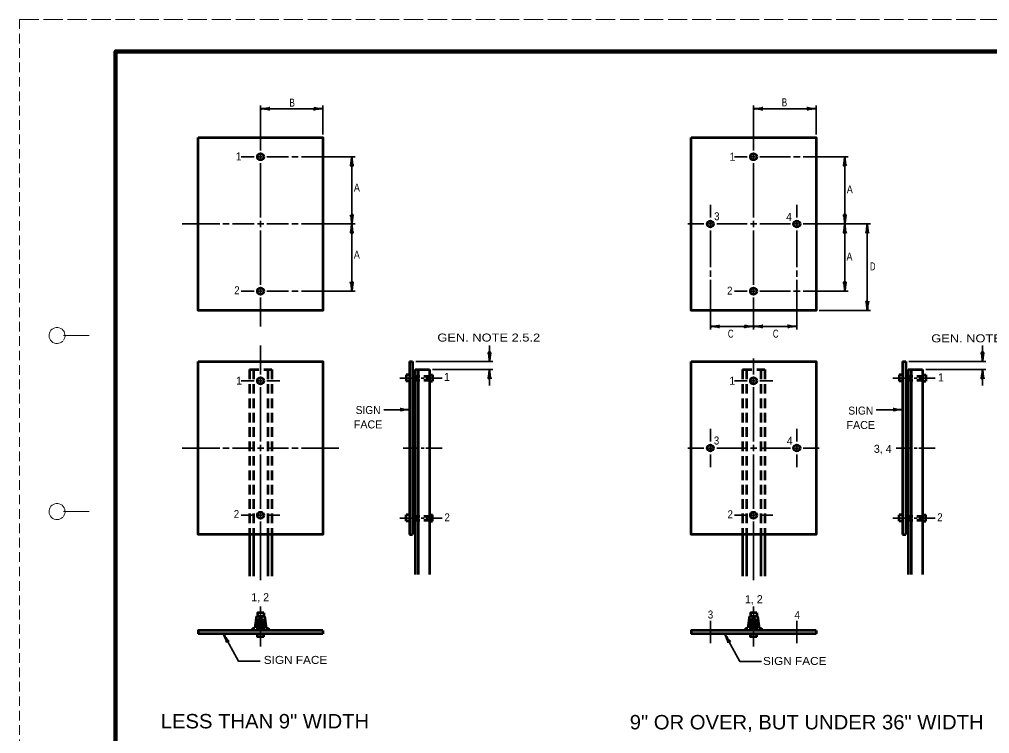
# Model space of a CAD drawing. Extents: x -45 to 635, y -378 to 62.
# Drawn here: x -45.3 to 257.7, y -160.7 to 62.5 of the extents above; entities that cross this region are included whole.
import ezdxf
from ezdxf.enums import TextEntityAlignment as Align

# ---------------------------------------------------------------- set-up
doc = ezdxf.new("R2010")
doc.units = 0
for name, pattern in [('LONG_DASHED', [7.5, 6, -1.5]), ('MEDIUM_DASHED', [4.5, 3, -1.5]), ('SHORT_DASHED', [2.7, 1.5, -1.2])]:
    doc.linetypes.add(name, pattern=pattern)
doc.layers.add('1', color=7, linetype='Continuous', lineweight=53)
doc.layers.add('61', color=7, linetype='Continuous', lineweight=35)

msp = doc.modelspace()

# ---------------------------------------------------------------- linework, layer by layer
at = {"layer": '1', "linetype": 'MEDIUM_DASHED', "lineweight": 13}
msp.add_line((-45.266, 62.46), (-45.326, -377.58), dxfattribs=at)
at = {"layer": '1', "lineweight": 35}
for p, q in [((29.979, 35.543), (29.979, 21.543)), ((29.979, 34.543), (49.479, 34.543)), ((49.479, 26.543), (49.479, 35.543)), ((183.951, 35.543), (183.951, 21.543)), ((183.951, 34.543), (203.451, 34.543)), ((203.451, 26.543), (203.451, 35.543)), ((23.979, 19.543), (27.979, 19.543)), ((29.479, 19.543), (30.479, 19.543)), ((29.979, 20.043), (29.979, 19.043)), ((31.979, 19.543), (38.729, 19.543)), ((39.729, 19.543), (41.729, 19.543)), ((42.729, 19.543), (59.479, 19.543)), ((177.951, 19.543), (181.951, 19.543)), ((183.451, 19.543), (184.451, 19.543)), ((183.951, 20.043), (183.951, 19.043)), ((185.951, 19.543), (195.451, 19.543)), ((196.451, 19.543), (198.451, 19.543)), ((199.451, 19.543), (213.451, 19.543)), ((29.979, 17.543), (29.979, 0.543)), ((183.951, 17.543), (183.951, 0.543)), ((170.451, 0.543), (170.451, 4.543)), ((197.451, 0.543), (197.451, 4.543)), ((5.479, -1.457), (17.229, -1.457)), ((18.229, -1.457), (20.229, -1.457)), ((21.229, -1.457), (27.979, -1.457)), ((28.979, -1.457), (30.979, -1.457)), ((29.979, -0.457), (29.979, -2.457)), ((31.979, -1.457), (38.729, -1.457)), ((39.729, -1.457), (41.729, -1.457)), ((42.729, -1.457), (59.479, -1.457)), ((163.451, -1.457), (168.451, -1.457)), ((169.951, -1.457), (170.951, -1.457)), ((170.451, -0.957), (170.451, -1.957)), ((172.451, -1.457), (181.951, -1.457)), ((182.951, -1.457), (184.951, -1.457)), ((183.951, -0.457), (183.951, -2.457)), ((185.951, -1.457), (195.451, -1.457)), ((196.951, -1.457), (197.951, -1.457)), ((197.451, -1.957), (197.451, -0.957)), ((199.451, -1.457), (220.451, -1.457)), ((219.451, -1.457), (219.451, -28.457)), ((29.979, -20.457), (29.979, -3.457)), ((170.451, -14.957), (170.451, -3.457)), ((183.951, -20.457), (183.951, -3.457)), ((197.451, -14.957), (197.451, -3.457)), ((170.451, -17.957), (170.451, -15.957)), ((197.451, -17.957), (197.451, -15.957)), ((170.451, -34.457), (170.451, -18.957)), ((197.451, -34.457), (197.451, -18.957)), ((23.979, -22.457), (27.979, -22.457)), ((29.479, -22.457), (30.479, -22.457)), ((29.979, -22.957), (29.979, -21.957)), ((31.979, -22.457), (38.729, -22.457)), ((39.729, -22.457), (41.729, -22.457)), ((42.729, -22.457), (59.479, -22.457)), ((177.951, -22.457), (181.951, -22.457)), ((183.451, -22.457), (184.451, -22.457)), ((183.951, -22.957), (183.951, -21.957)), ((185.951, -22.457), (195.451, -22.457)), ((196.451, -22.457), (198.451, -22.457)), ((199.451, -22.457), (213.451, -22.457)), ((29.979, -33.457), (29.979, -24.457)), ((183.951, -34.457), (183.951, -24.457)), ((204.451, -28.457), (220.451, -28.457)), ((29.979, -39.457), (29.979, -48.457)), ((101.479, -44.457), (101.479, -39.457)), ((255.451, -44.457), (255.451, -39.457)), ((78.479, -44.457), (102.479, -44.457)), ((183.951, -43.457), (183.951, -48.457)), ((232.451, -44.457), (256.451, -44.457)), ((83.729, -46.957), (102.479, -46.957)), ((101.479, -46.957), (101.479, -51.957)), ((237.701, -46.957), (256.451, -46.957)), ((255.451, -46.957), (255.451, -51.957)), ((23.979, -50.457), (27.979, -50.457)), ((29.479, -50.457), (30.479, -50.457)), ((29.979, -49.957), (29.979, -50.957)), ((31.979, -50.457), (35.979, -50.457)), ((79.604, -49.582), (73.479, -49.582)), ((81.104, -49.582), (80.104, -49.582)), ((86.729, -49.582), (81.604, -49.582)), ((177.951, -50.457), (181.951, -50.457)), ((183.451, -50.457), (184.451, -50.457)), ((183.951, -49.957), (183.951, -50.957)), ((185.951, -50.457), (189.951, -50.457)), ((233.576, -49.582), (227.451, -49.582)), ((235.076, -49.582), (234.076, -49.582)), ((240.701, -49.582), (235.576, -49.582)), ((29.979, -52.457), (29.979, -69.457)), ((183.951, -52.457), (183.951, -69.457)), ((76.479, -59.487), (68.479, -59.487)), ((230.451, -59.487), (222.249, -59.487)), ((170.451, -69.457), (170.451, -65.457)), ((197.451, -69.457), (197.451, -65.457)), ((5.479, -71.457), (17.229, -71.457)), ((18.229, -71.457), (20.229, -71.457)), ((21.229, -71.457), (27.979, -71.457)), ((28.979, -71.457), (30.979, -71.457)), ((29.979, -70.457), (29.979, -72.457)), ((31.979, -71.457), (38.729, -71.457)), ((39.729, -71.457), (41.729, -71.457)), ((42.729, -71.457), (54.479, -71.457)), ((74.479, -71.457), (79.604, -71.457)), ((80.104, -71.457), (81.104, -71.457)), ((81.604, -71.457), (86.729, -71.457)), ((163.451, -71.457), (168.451, -71.457)), ((169.951, -71.457), (170.951, -71.457)), ((170.451, -70.957), (170.451, -71.957)), ((172.451, -71.457), (181.951, -71.457)), ((182.951, -71.457), (184.951, -71.457)), ((183.951, -70.457), (183.951, -72.457)), ((185.951, -71.457), (195.451, -71.457)), ((196.951, -71.457), (197.951, -71.457)), ((197.451, -71.957), (197.451, -70.957)), ((199.451, -71.457), (204.451, -71.457)), ((228.451, -71.457), (233.576, -71.457)), ((234.076, -71.457), (235.076, -71.457)), ((235.576, -71.457), (240.701, -71.457)), ((29.979, -90.457), (29.979, -73.457)), ((170.451, -73.457), (170.451, -77.457)), ((183.951, -90.457), (183.951, -73.457)), ((197.451, -73.457), (197.451, -77.457)), ((23.979, -92.457), (27.979, -92.457)), ((29.479, -92.457), (30.479, -92.457)), ((29.979, -92.957), (29.979, -91.957)), ((31.979, -92.457), (35.979, -92.457)), ((79.604, -93.332), (73.479, -93.332)), ((81.104, -93.332), (80.104, -93.332)), ((86.729, -93.332), (81.604, -93.332)), ((177.951, -92.457), (181.951, -92.457)), ((183.451, -92.457), (184.451, -92.457)), ((183.951, -92.957), (183.951, -91.957)), ((185.951, -92.457), (189.951, -92.457)), ((233.576, -93.332), (227.451, -93.332)), ((235.076, -93.332), (234.076, -93.332)), ((240.701, -93.332), (235.576, -93.332)), ((29.979, -112.721), (29.979, -94.457)), ((183.951, -112.721), (183.951, -94.457)), ((29.979, -125.582), (29.979, -120.953)), ((183.951, -125.582), (183.951, -120.953)), ((29.979, -127.082), (29.979, -126.082)), ((170.451, -127.957), (170.451, -125.457)), ((183.951, -127.082), (183.951, -126.082)), ((197.451, -127.957), (197.451, -125.457)), ((29.979, -133.457), (29.979, -127.582)), ((170.451, -128.457), (170.451, -129.457)), ((170.451, -132.457), (170.451, -129.957)), ((183.951, -133.457), (183.951, -127.582)), ((197.451, -128.457), (197.451, -129.457)), ((197.451, -132.457), (197.451, -129.957))]:
    msp.add_line(p, q, dxfattribs=at)
at = {"layer": '1'}
for p, q in [((76.479, -44.457), (76.479, -98.457)), ((76.479, -44.457), (77.479, -44.457)), ((77.479, -44.457), (77.479, -98.457)), ((230.451, -44.457), (230.451, -98.457)), ((230.451, -44.457), (231.451, -44.457)), ((231.451, -44.457), (231.451, -98.457)), ((78.229, -46.957), (78.229, -110.957)), ((78.229, -46.957), (82.729, -46.957)), ((79.229, -46.957), (79.229, -110.957)), ((82.729, -46.957), (82.729, -110.957)), ((232.201, -46.957), (232.201, -110.957)), ((232.201, -46.957), (236.701, -46.957)), ((233.201, -46.957), (233.201, -110.957)), ((236.701, -46.957), (236.701, -110.957)), ((75.479, -48.582), (75.479, -50.582)), ((76.479, -48.582), (75.479, -48.582)), ((76.479, -50.582), (75.479, -50.582)), ((82.729, -48.582), (83.729, -48.582)), ((82.729, -50.582), (83.729, -50.582)), ((83.729, -48.582), (83.729, -50.582)), ((229.451, -48.582), (229.451, -50.582)), ((230.451, -48.582), (229.451, -48.582)), ((230.451, -50.582), (229.451, -50.582)), ((236.701, -48.582), (237.701, -48.582)), ((236.701, -50.582), (237.701, -50.582)), ((237.701, -48.582), (237.701, -50.582)), ((75.479, -94.332), (75.479, -92.332)), ((76.479, -92.332), (75.479, -92.332)), ((82.729, -92.332), (83.729, -92.332)), ((83.729, -94.332), (83.729, -92.332)), ((229.451, -94.332), (229.451, -92.332)), ((230.451, -92.332), (229.451, -92.332)), ((236.701, -92.332), (237.701, -92.332)), ((237.701, -94.332), (237.701, -92.332)), ((76.479, -94.332), (75.479, -94.332)), ((82.729, -94.332), (83.729, -94.332)), ((230.451, -94.332), (229.451, -94.332)), ((236.701, -94.332), (237.701, -94.332)), ((26.479, -98.457), (26.479, -111.457)), ((27.729, -98.457), (27.729, -111.457)), ((32.229, -98.457), (32.229, -111.457)), ((33.479, -98.457), (33.479, -111.457)), ((76.479, -98.457), (77.479, -98.457)), ((180.451, -98.457), (180.451, -111.457)), ((181.701, -98.457), (181.701, -111.457)), ((186.201, -98.457), (186.201, -111.457)), ((187.451, -98.457), (187.451, -111.457)), ((230.451, -98.457), (231.451, -98.457)), ((28.726, -123.957), (28.191, -127.707)), ((28.726, -123.957), (31.231, -123.957)), ((30.979, -122.953), (30.979, -123.953)), ((31.231, -123.957), (31.767, -127.707)), ((182.699, -123.957), (182.163, -127.707)), ((182.699, -123.957), (185.204, -123.957)), ((184.951, -122.953), (184.951, -123.953)), ((185.204, -123.957), (185.739, -127.707)), ((29.377, -124.707), (28.841, -128.457)), ((29.377, -124.707), (30.581, -124.707)), ((29.604, -128.457), (29.604, -124.707)), ((30.354, -128.457), (30.354, -124.707)), ((30.581, -124.707), (31.117, -128.457)), ((183.349, -124.707), (182.813, -128.457)), ((183.349, -124.707), (184.553, -124.707)), ((183.576, -128.457), (183.576, -124.707)), ((184.326, -128.457), (184.326, -124.707)), ((184.553, -124.707), (185.089, -128.457)), ((49.479, -129.457), (10.479, -129.457)), ((27.479, -127.707), (27.479, -128.457)), ((27.479, -127.707), (28.191, -127.707)), ((30.979, -130.457), (30.979, -129.457)), ((31.767, -127.707), (32.479, -127.707)), ((32.479, -127.707), (32.479, -128.457)), ((49.479, -128.457), (49.479, -129.457)), ((203.451, -129.457), (164.451, -129.457)), ((181.451, -127.707), (181.451, -128.457)), ((181.451, -127.707), (182.163, -127.707)), ((184.951, -130.457), (184.951, -129.457)), ((185.739, -127.707), (186.451, -127.707)), ((186.451, -127.707), (186.451, -128.457)), ((203.451, -128.457), (203.451, -129.457))]:
    msp.add_line(p, q, dxfattribs=at)
at = {"layer": '1', "linetype": 'MEDIUM_DASHED'}
for p, q in [((26.479, -46.957), (33.479, -46.957)), ((26.479, -46.957), (26.479, -98.457)), ((27.729, -46.957), (27.729, -98.457)), ((32.229, -46.957), (32.229, -98.457)), ((33.479, -46.957), (33.479, -98.457)), ((180.451, -46.957), (187.451, -46.957)), ((180.451, -46.957), (180.451, -98.457)), ((181.701, -46.957), (181.701, -98.457)), ((186.201, -46.957), (186.201, -98.457)), ((187.451, -46.957), (187.451, -98.457))]:
    msp.add_line(p, q, dxfattribs=at)
at = {"layer": '1', "linetype": 'SHORT_DASHED'}
for p, q in [((78.229, -48.957), (82.729, -48.957)), ((78.229, -50.207), (82.729, -50.207)), ((232.201, -48.957), (236.701, -48.957)), ((232.201, -50.207), (236.701, -50.207)), ((78.229, -92.707), (82.729, -92.707)), ((232.201, -92.707), (236.701, -92.707)), ((78.229, -93.957), (82.729, -93.957)), ((232.201, -93.957), (236.701, -93.957))]:
    msp.add_line(p, q, dxfattribs=at)
at = {"layer": '1'}
for points in [[(10.479, 25.543), (49.479, 25.543), (49.479, -28.457), (10.479, -28.457)], [(164.451, 25.543), (203.451, 25.543), (203.451, -28.457), (164.451, -28.457)], [(10.479, -44.457), (49.479, -44.457), (49.479, -98.457), (10.479, -98.457)], [(164.451, -44.457), (203.451, -44.457), (203.451, -98.457), (164.451, -98.457)]]:
    msp.add_lwpolyline(points, close=True, dxfattribs=at)
at = {"layer": '1', "lineweight": 35}
for points in [[(58.479, 19.543), (58.479, -1.457), (58.479, -22.457)], [(212.451, -22.457), (212.451, -1.457), (212.451, 19.543)], [(170.451, -33.457), (183.951, -33.457), (197.451, -33.457)], [(18.365, -129.457), (23.051, -138), (29.814, -138)], [(174.966, -129.579), (179.652, -138.122), (186.416, -138.122)]]:
    msp.add_lwpolyline(points, dxfattribs=at)
at = {"layer": '1'}
for points in [[(30.979, -122.953), (28.979, -122.953), (28.979, -123.953)], [(184.951, -122.953), (182.951, -122.953), (182.951, -123.953)], [(49.479, -128.457), (10.479, -128.457), (10.479, -129.457)], [(30.979, -130.457), (28.979, -130.457), (28.979, -129.457)], [(203.451, -128.457), (164.451, -128.457), (164.451, -129.457)], [(184.951, -130.457), (182.951, -130.457), (182.951, -129.457)]]:
    msp.add_lwpolyline(points, dxfattribs=at)
for centre in [(29.979, 19.543), (183.951, 19.543), (170.451, -1.457), (197.451, -1.457), (29.979, -22.457), (183.951, -22.457), (29.979, -50.457), (183.951, -50.457), (170.451, -71.457), (197.451, -71.457), (29.979, -92.457), (183.951, -92.457)]:
    msp.add_circle(centre, 1, dxfattribs=at)
at = {"layer": '1', "lineweight": 40}
for centre, major_axis, ratio, start_param, end_param in [((31.099, 34.332), (-1.756, 0.176), 0.07063, 3.1407148, 5.41811), ((31.07, 34.82), (-1.786, -0.156), 0.122415, 0.8963533, 3.1415927), ((48.388, 34.267), (1.786, 0.156), 0.122415, 0.8963533, 3.1415927), ((48.358, 34.755), (1.756, -0.176), 0.07063, 3.1407148, 5.41811), ((185.042, 34.82), (-1.786, -0.156), 0.122415, 0.8963533, 3.1415927), ((185.072, 34.332), (-1.756, 0.176), 0.07063, 3.1407148, 5.41811), ((202.36, 34.267), (1.786, 0.156), 0.122415, 0.8963533, 3.1415927), ((202.331, 34.755), (1.756, -0.176), 0.07063, 3.1407148, 5.41811), ((58.267, 18.423), (0.176, 1.756), 0.07063, 3.1407148, 5.41811), ((58.267, 18.423), (0.176, 1.756), 0.07063, 3.1407148, 5.41811), ((58.755, 18.452), (-0.156, 1.786), 0.122415, 0.8963533, 3.1415927), ((58.755, 18.452), (-0.156, 1.786), 0.122415, 0.8963533, 3.1415927), ((212.24, 18.423), (0.176, 1.756), 0.07063, 3.1407148, 5.41811), ((212.24, 18.423), (0.176, 1.756), 0.07063, 3.1407148, 5.41811), ((212.727, 18.452), (-0.156, 1.786), 0.122415, 0.8963533, 3.1415927), ((212.727, 18.452), (-0.156, 1.786), 0.122415, 0.8963533, 3.1415927), ((58.203, -0.365), (0.156, -1.786), 0.122415, 0.8963533, 3.1415927), ((58.203, -0.365), (0.156, -1.786), 0.122415, 0.8963533, 3.1415927), ((58.69, -0.336), (-0.176, -1.756), 0.07063, 3.1407148, 5.41811), ((58.69, -0.336), (-0.176, -1.756), 0.07063, 3.1407148, 5.41811), ((212.175, -0.365), (0.156, -1.786), 0.122415, 0.8963533, 3.1415927), ((212.175, -0.365), (0.156, -1.786), 0.122415, 0.8963533, 3.1415927), ((212.663, -0.336), (-0.176, -1.756), 0.07063, 3.1407148, 5.41811), ((212.663, -0.336), (-0.176, -1.756), 0.07063, 3.1407148, 5.41811), ((58.267, -2.577), (0.176, 1.756), 0.07063, 3.1407148, 5.41811), ((58.267, -2.577), (0.176, 1.756), 0.07063, 3.1407148, 5.41811), ((58.755, -2.548), (-0.156, 1.786), 0.122415, 0.8963533, 3.1415927), ((58.755, -2.548), (-0.156, 1.786), 0.122415, 0.8963533, 3.1415927), ((212.24, -2.577), (0.176, 1.756), 0.07063, 3.1407148, 5.41811), ((212.24, -2.577), (0.176, 1.756), 0.07063, 3.1407148, 5.41811), ((212.727, -2.548), (-0.156, 1.786), 0.122415, 0.8963533, 3.1415927), ((212.727, -2.548), (-0.156, 1.786), 0.122415, 0.8963533, 3.1415927), ((219.24, -2.577), (0.176, 1.756), 0.07063, 3.1407148, 5.41811), ((219.24, -2.577), (0.176, 1.756), 0.07063, 3.1407148, 5.41811), ((219.727, -2.548), (-0.156, 1.786), 0.122415, 0.8963533, 3.1415927), ((219.727, -2.548), (-0.156, 1.786), 0.122415, 0.8963533, 3.1415927), ((58.203, -21.365), (0.156, -1.786), 0.122415, 0.8963533, 3.1415927), ((58.69, -21.336), (-0.176, -1.756), 0.07063, 3.1407148, 5.41811), ((212.175, -21.365), (0.156, -1.786), 0.122415, 0.8963533, 3.1415927), ((212.175, -21.365), (0.156, -1.786), 0.122415, 0.8963533, 3.1415927), ((212.663, -21.336), (-0.176, -1.756), 0.07063, 3.1407148, 5.41811), ((212.663, -21.336), (-0.176, -1.756), 0.07063, 3.1407148, 5.41811), ((219.175, -27.365), (0.156, -1.786), 0.122415, 0.8963533, 3.1415927), ((219.175, -27.365), (0.156, -1.786), 0.122415, 0.8963533, 3.1415927), ((219.663, -27.336), (-0.176, -1.756), 0.07063, 3.1407148, 5.41811), ((219.663, -27.336), (-0.176, -1.756), 0.07063, 3.1407148, 5.41811), ((171.542, -33.18), (-1.786, -0.156), 0.122415, 0.8963533, 3.1415927), ((171.542, -33.18), (-1.786, -0.156), 0.122415, 0.8963533, 3.1415927), ((182.831, -33.245), (1.756, -0.176), 0.07063, 3.1407148, 5.41811), ((182.831, -33.245), (1.756, -0.176), 0.07063, 3.1407148, 5.41811), ((185.042, -33.18), (-1.786, -0.156), 0.122415, 0.8963533, 3.1415927), ((185.042, -33.18), (-1.786, -0.156), 0.122415, 0.8963533, 3.1415927), ((196.331, -33.245), (1.756, -0.176), 0.07063, 3.1407148, 5.41811), ((171.572, -33.668), (-1.756, 0.176), 0.07063, 3.1407148, 5.41811), ((171.572, -33.668), (-1.756, 0.176), 0.07063, 3.1407148, 5.41811), ((182.86, -33.733), (1.786, 0.156), 0.122415, 0.8963533, 3.1415927), ((182.86, -33.733), (1.786, 0.156), 0.122415, 0.8963533, 3.1415927), ((185.072, -33.668), (-1.756, 0.176), 0.07063, 3.1407148, 5.41811), ((185.072, -33.668), (-1.756, 0.176), 0.07063, 3.1407148, 5.41811), ((196.36, -33.733), (1.786, 0.156), 0.122415, 0.8963533, 3.1415927), ((101.203, -43.365), (0.156, -1.786), 0.122415, 0.8963533, 3.1415927), ((101.69, -43.336), (-0.176, -1.756), 0.07063, 3.1407148, 5.41811), ((255.175, -43.365), (0.156, -1.786), 0.122415, 0.8963533, 3.1415927), ((255.663, -43.336), (-0.176, -1.756), 0.07063, 3.1407148, 5.41811), ((101.267, -48.077), (0.176, 1.756), 0.07063, 3.1407148, 5.41811), ((101.755, -48.048), (-0.156, 1.786), 0.122415, 0.8963533, 3.1415927), ((255.24, -48.077), (0.176, 1.756), 0.07063, 3.1407148, 5.41811), ((255.727, -48.048), (-0.156, 1.786), 0.122415, 0.8963533, 3.1415927), ((75.388, -59.763), (1.786, 0.156), 0.122415, 0.8963533, 3.1415927), ((75.358, -59.275), (1.756, -0.176), 0.07063, 3.1407148, 5.41811), ((229.36, -59.763), (1.786, 0.156), 0.122415, 0.8963533, 3.1415927), ((229.331, -59.275), (1.756, -0.176), 0.07063, 3.1407148, 5.41811), ((18.718, -130.541), (-0.691, 1.624), 0.07063, 3.1407148, 5.41811), ((19.132, -130.281), (-0.996, 1.491), 0.122415, 0.8963533, 3.1415927), ((175.319, -130.663), (-0.691, 1.624), 0.07063, 3.1407148, 5.41811), ((175.733, -130.403), (-0.996, 1.491), 0.122415, 0.8963533, 3.1415927)]:
    msp.add_ellipse(centre, major_axis=major_axis, ratio=ratio, start_param=start_param, end_param=end_param, dxfattribs=at)
at = {"layer": '61', "linetype": 'LONG_DASHED', "lineweight": 13}
msp.add_line((-45.266, 62.46), (634.754, 62.46), dxfattribs=at)
at = {"layer": '61', "lineweight": 13}
for p, q in [((-31.546, -36.3), (-23.566, -36.28)), ((-31.566, -91.3), (-23.566, -91.3))]:
    msp.add_line(p, q, dxfattribs=at)
at = {"layer": '61', "lineweight": 158}
msp.add_lwpolyline([(623.774, 52.46), (-15.266, 52.46), (-15.266, -367.56)], dxfattribs=at)
at = {"layer": '61', "lineweight": 13}
for centre, end in [((-33.568, -36.298), 316.23216), ((-33.568, -91.298), 315.37577)]:
    msp.add_arc(centre, 2.5, 323.13009, end, dxfattribs=at)

# ---------------------------------------------------------------- texts
at = {"layer": '1'}
for s, width, p in [('B', 0.75, (39.01, 35.192)), ('A', 0.85, (59.107, 8.639)), ('A', 0.85, (59.107, -12.318)), ('2', 0.9, (21.756, -23.413)), ('2', 0.9, (21.62, -93.336)), ('2', 0.9, (87.414, -94.367))]:
    msp.add_text(s, height=2.5, dxfattribs=dict(at, width=width)).set_placement(p)
for s, height, width, p in [('B', 2.5, 0.75, (193.588, 35.282)), ('A', 2.5, 0.85, (213.996, 8.096)), ('3', 2.5, 0.9, (172.473, -0.292)), ('4', 2.5, 0.95, (195.003, -0.494)), ('A', 2.5, 0.85, (213.895, -12.925)), ('D', 2.5, 0.7, (221.17, -15.957)), ('2', 2.5, 0.9, (176.514, -23.536)), ('GEN. NOTE 2.5.2', 2.5, 1.2, (101.25, -38.194)), ('C', 2.5, 0.75, (176.817, -36.978)), ('C', 2.5, 0.75, (190.861, -36.978)), ('GEN. NOTE 2.5.2', 2.5, 1.2, (255.475, -38.438)), ('SIGN', 2.5, 0.95, (63.569, -60.827)), ('SIGN', 2.5, 0.95, (217.421, -61.01)), ('3', 2.5, 0.9, (172.381, -70.352)), ('4', 2.5, 0.95, (195.214, -70.456)), ('2', 2.5, 0.9, (176.656, -93.4)), ('2', 2.5, 0.9, (242.13, -94.339)), ('3', 2.5, 0.9, (170.495, -124.726)), ('4', 2.5, 0.95, (197.592, -124.849)), ('SIGN FACE', 2.5, 1.1, (40.902, -138.905)), ('SIGN FACE', 2.5, 1.1, (196.794, -139.231)), ('LESS THAN 9" WIDTH', 4.5, 1.05, (31.352, -159.047)), ('LESS THAN 9" WIDTH', 4.5, 1.05, (31.352, -159.047)), ('9" OR OVER, BUT UNDER 36" WIDTH', 4.5, 1.05, (200.523, -159.359))]:
    msp.add_text(s, height=height, dxfattribs=dict(at, width=width)).set_placement(p, align=Align.CENTER)
for p in [(22.23, 18.407), (87.267, -50.49), (22.356, -51.668)]:
    msp.add_text('1', height=2.5, dxfattribs=at).set_placement(p)
for s, p in [('1', (177.359, 18.304)), ('1', (242.46, -50.64)), ('1', (177.298, -51.683)), ('FACE', (63.569, -65.327)), ('FACE', (217.421, -65.51)), ('3, 4', (224.302, -72.959)), ('1, 2', (29.863, -119.322)), ('1, 2', (184.013, -119.931))]:
    msp.add_text(s, height=2.5, dxfattribs=at).set_placement(p, align=Align.CENTER)

doc.saveas('drawing.dxf')
